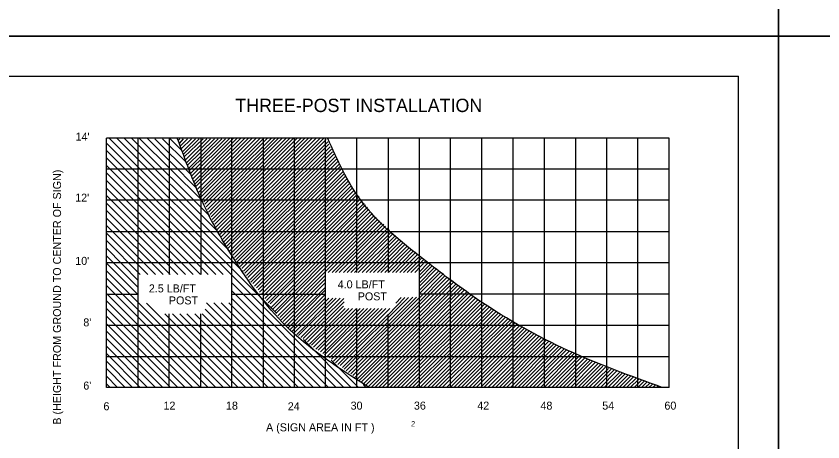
# Model space of a CAD drawing. Extents: x 644358 to 648627, y 294594 to 295782.
# Drawn here: x 645754.7 to 646056.9, y 295035.6 to 295195.1 of the extents above; entities that cross this region are included whole.
import ezdxf

# ---------------------------------------------------------------- set-up
doc = ezdxf.new("R2010")
doc.units = 0
for name, color, linetype in [('1', 7, 'Continuous'), ('10', 7, 'Continuous'), ('2', 7, 'Continuous'), ('4', 7, 'Continuous'), ('PLT-BNDY', 7, 'Continuous')]:
    doc.layers.add(name, color=color, linetype=linetype)

msp = doc.modelspace()

# ---------------------------------------------------------------- linework, layer by layer
at = {"layer": '1'}
for p, q in [((645239.31, 295172.63), (646025.31, 295172.63)), ((646025.31, 294608.63), (646025.31, 295172.63)), ((645845.96, 295090.75), (645845.96, 295090.75)), ((645859.21, 295079.5), (645859.21, 295079.5)), ((645872.21, 295067.63), (645872.21, 295067.63))]:
    msp.add_line(p, q, dxfattribs=at)
at = {"layer": '10'}
for p, q in [((645839.59, 295099.38), (645789.59, 295149.38)), ((645834.21, 295107.5), (645792.46, 295149.38)), ((645830.21, 295114.38), (645795.21, 295149.38)), ((645827.21, 295120.13), (645798.09, 295149.25)), ((645824.34, 295126), (645800.96, 295149.25)), ((645822.21, 295130.75), (645803.96, 295149.25)), ((645820.21, 295135.75), (645806.71, 295149.13)), ((645818.46, 295140.38), (645809.59, 295149.13)), ((645816.84, 295144.75), (645812.46, 295149.13)), ((645815.46, 295148.5), (645816.09, 295149.13)), ((645815.96, 295147.38), (645817.46, 295149.13)), ((645816.21, 295146.38), (645818.96, 295149.13)), ((645816.59, 295145.38), (645820.46, 295149.13)), ((645817.09, 295144.25), (645821.84, 295149.13)), ((645817.46, 295143.38), (645823.21, 295149.13)), ((645817.71, 295142.38), (645824.71, 295149.13)), ((645818.21, 295141.25), (645826.09, 295149.13)), ((645818.59, 295140.25), (645827.46, 295149.13)), ((645818.96, 295139.25), (645828.96, 295149.13)), ((645819.34, 295138.13), (645830.34, 295149.13)), ((645819.71, 295137.25), (645831.71, 295149.13)), ((645820.21, 295136.25), (645833.09, 295149.13)), ((645820.46, 295135.13), (645834.59, 295149.25)), ((645820.84, 295134.13), (645835.96, 295149.25)), ((645821.34, 295133.13), (645837.34, 295149.25)), ((645821.71, 295132.13), (645838.71, 295149.25)), ((645821.96, 295131.13), (645840.21, 295149.25)), ((645822.59, 295130.25), (645841.59, 295149.25)), ((645823.09, 295129.13), (645842.96, 295149.25)), ((645823.46, 295128.25), (645844.46, 295149.25)), ((645823.96, 295127.38), (645845.96, 295149.25)), ((645824.46, 295126.38), (645847.34, 295149.25)), ((645824.96, 295125.5), (645848.71, 295149.25)), ((645825.34, 295124.63), (645850.21, 295149.25)), ((645825.84, 295123.63), (645851.59, 295149.25)), ((645826.34, 295122.63), (645852.96, 295149.38)), ((645826.71, 295121.63), (645854.34, 295149.38)), ((645827.21, 295120.75), (645855.84, 295149.38)), ((645827.71, 295119.88), (645857.21, 295149.38)), ((645828.09, 295118.88), (645858.59, 295149.38)), ((645828.59, 295118), (645859.96, 295149.38)), ((645829.09, 295117.13), (645861.46, 295149.38)), ((645829.46, 295116), (645862.84, 295149.38)), ((645829.96, 295115.13), (645864.21, 295149.38)), ((645830.46, 295114.13), (645865.59, 295149.38)), ((645830.96, 295113.25), (645867.09, 295149.38)), ((645831.46, 295112.38), (645868.59, 295149.38)), ((645831.96, 295111.38), (645869.96, 295149.38)), ((645832.46, 295110.5), (645870.84, 295148.88)), ((645852.13, 295083.96), (645788.59, 295147.5)), ((645832.96, 295109.63), (645871.46, 295148)), ((645833.59, 295108.88), (645871.84, 295147.13)), ((645834.09, 295108.13), (645872.34, 295146.13)), ((645834.71, 295107.13), (645872.84, 295145.25)), ((645830.82, 295102.63), (645788.59, 295144.75)), ((645832.28, 295098.31), (645788.59, 295142)), ((645835.34, 295106.38), (645873.21, 295144.25)), ((645835.84, 295105.5), (645873.71, 295143.38)), ((645836.46, 295104.63), (645874.34, 295142.5)), ((645829.53, 295098.31), (645788.59, 295139.13)), ((645836.96, 295103.75), (645874.71, 295141.5)), ((645837.46, 295103), (645875.21, 295140.63)), ((645838.09, 295102.13), (645875.71, 295139.63)), ((645826.65, 295098.31), (645788.59, 295136.38)), ((645838.59, 295101.25), (645876.09, 295138.75)), ((645839.21, 295100.5), (645876.59, 295137.88)), ((645839.84, 295099.5), (645877.21, 295136.88)), ((645840.34, 295098.75), (645877.59, 295136)), ((645823.78, 295098.31), (645788.59, 295133.5)), ((645840.96, 295097.88), (645878.09, 295135.13)), ((645841.46, 295097.13), (645878.59, 295134.13)), ((645842.09, 295096.13), (645879.09, 295133.25)), ((645821.03, 295098.31), (645788.59, 295130.63)), ((645842.59, 295095.38), (645879.46, 295132.25)), ((645843.38, 295094.92), (645880.09, 295131.38)), ((645844.05, 295093.97), (645880.59, 295130.63)), ((645818.15, 295098.31), (645788.59, 295127.88)), ((645844.74, 295093.28), (645881.21, 295129.75)), ((645845.4, 295092.57), (645881.96, 295129)), ((645845.92, 295091.71), (645882.46, 295128.25)), ((645846.73, 295091.02), (645883.21, 295127.5)), ((645815.28, 295098.31), (645788.59, 295125)), ((645847.28, 295090.19), (645883.71, 295126.63)), ((645847.91, 295089.33), (645884.34, 295125.88)), ((645848.46, 295088.62), (645885.09, 295125)), ((645849.16, 295087.7), (645885.59, 295124.38)), ((645812.4, 295098.31), (645788.59, 295122.25)), ((645849.86, 295087.27), (645886.34, 295123.5)), ((645850.09, 295085.88), (645886.84, 295122.75)), ((645850.71, 295085.25), (645887.46, 295121.88)), ((645869.65, 295102.63), (645888.09, 295121.13)), ((645809.78, 295098.31), (645788.59, 295119.38)), ((645870.27, 295099.06), (645890.21, 295119)), ((645870.97, 295102.63), (645888.84, 295120.38)), ((645871.65, 295099.06), (645890.96, 295118.38)), ((645872.46, 295102.63), (645889.59, 295119.75)), ((645806.9, 295098.31), (645788.59, 295116.63)), ((645873.03, 295099.06), (645891.71, 295117.63)), ((645874.4, 295099.06), (645892.46, 295117.13)), ((645875.77, 295099.06), (645893.09, 295116.38)), ((645877.28, 295099.06), (645893.96, 295115.63)), ((645878.65, 295099.06), (645894.59, 295115)), ((645804.03, 295098.31), (645788.59, 295113.75)), ((645880.03, 295099.06), (645895.34, 295114.25)), ((645881.4, 295099.06), (645895.96, 295113.63)), ((645882.79, 295099.06), (645896.84, 295112.88)), ((645884.27, 295099.06), (645897.46, 295112.25)), ((645801.16, 295098.31), (645788.59, 295111)), ((645885.77, 295099.06), (645898.21, 295111.5)), ((645887.15, 295099.06), (645898.96, 295110.88)), ((645888.52, 295099.06), (645899.71, 295110.25)), ((645890.02, 295099.06), (645900.46, 295109.63)), ((645891.28, 295099.06), (645901.34, 295109)), ((645800.46, 295096.1), (645788.59, 295108.13)), ((645892.77, 295099.06), (645902.09, 295108.38)), ((645894.15, 295099.06), (645902.84, 295107.75)), ((645895.64, 295099.06), (645903.59, 295107.13)), ((645896.9, 295099.06), (645904.46, 295106.63)), ((645898.4, 295099.06), (645905.21, 295105.88)), ((645800.46, 295093.38), (645788.59, 295105.25)), ((645899.78, 295099.06), (645906.09, 295105.25)), ((645901.17, 295099.06), (645906.84, 295104.63)), ((645902.53, 295099.06), (645907.59, 295104)), ((645904, 295099.06), (645908.34, 295103.5)), ((645905.84, 295099.35), (645909.02, 295102.74)), ((645908.97, 295102.63), (645909.09, 295102.75)), ((645800.46, 295090.63), (645788.59, 295102.5)), ((645877.46, 295056), (645830.84, 295102.63)), ((645851.46, 295084.38), (645869.65, 295102.63)), ((645851.96, 295083.75), (645870.59, 295102.25)), ((645852.71, 295082.88), (645872.46, 295102.63)), ((645905.84, 295098), (645909.96, 295102.13)), ((645905.84, 295096.75), (645910.71, 295101.63)), ((645905.84, 295095.25), (645911.46, 295100.88)), ((645905.84, 295094), (645912.21, 295100.38)), ((645800.46, 295087.79), (645788.59, 295099.63)), ((645797.39, 295088.08), (645788.59, 295096.88)), ((645853.46, 295082.25), (645870.59, 295099.38)), ((645853.96, 295081.38), (645870.59, 295098)), ((645905.84, 295092.38), (645913.09, 295099.63)), ((645905.84, 295091.13), (645913.84, 295099.13)), ((645905.84, 295089.63), (645914.71, 295098.5)), ((645905.84, 295088.25), (645915.33, 295097.75)), ((645905.84, 295086.98), (645916.03, 295097.22)), ((645826.59, 295056), (645788.59, 295094.13)), ((645874.59, 295056), (645835.46, 295095.13)), ((645854.71, 295080.75), (645870.59, 295096.63)), ((645855.34, 295079.88), (645870.59, 295095.27)), ((645880.85, 295060.51), (645916.9, 295096.56)), ((645881.6, 295059.76), (645917.84, 295096)), ((645882.57, 295059.24), (645918.59, 295095.38)), ((645883.28, 295058.69), (645919.46, 295094.75)), ((645884.11, 295058.03), (645920.21, 295094.13)), ((645823.71, 295056), (645788.59, 295091.25)), ((645871.71, 295056), (645835.46, 295092.25)), ((645856.09, 295079.25), (645870.59, 295093.61)), ((645856.59, 295078.38), (645870.59, 295092.51)), ((645857.34, 295077.75), (645870.59, 295091)), ((645884.71, 295057.25), (645920.96, 295093.5)), ((645885.59, 295056.75), (645921.71, 295092.88)), ((645886.59, 295056.25), (645922.59, 295092.38)), ((645887.84, 295056.13), (645923.46, 295091.75)), ((645889.21, 295056.13), (645924.21, 295091.25)), ((645820.96, 295056), (645788.59, 295088.5)), ((645829.46, 295056), (645797.2, 295088.26)), ((645832.34, 295056), (645800.41, 295087.83)), ((645857.71, 295056), (645825.96, 295087.75)), ((645860.46, 295056), (645828.73, 295087.74)), ((645863.21, 295056), (645831.48, 295087.74)), ((645866.09, 295056), (645834.35, 295087.74)), ((645868.84, 295056), (645835.46, 295089.38)), ((645857.96, 295077), (645870.59, 295089.63)), ((645858.59, 295076.25), (645871.79, 295089.45)), ((645859.82, 295075.87), (645873.29, 295089.45)), ((645860.5, 295075.41), (645874.65, 295089.45)), ((645861.38, 295074.67), (645876.04, 295089.45)), ((645862.26, 295074.29), (645877.46, 295089.38)), ((645863.03, 295073.57), (645877.59, 295088.13)), ((645876.05, 295064.21), (645901.64, 295089.65)), ((645876.91, 295063.45), (645903.29, 295089.83)), ((645877.57, 295062.85), (645904.66, 295089.83)), ((645878.34, 295062.25), (645905.92, 295089.83)), ((645879.22, 295061.64), (645907.42, 295089.83)), ((645880.08, 295061.12), (645908.67, 295089.83)), ((645890.59, 295056.13), (645925.21, 295090.63)), ((645891.96, 295056.13), (645925.96, 295090.13)), ((645893.46, 295056.13), (645926.84, 295089.5)), ((645894.14, 295083.33), (645900.34, 295089.75)), ((645894.84, 295056.13), (645927.71, 295088.88)), ((645896.21, 295056.13), (645928.59, 295088.5)), ((645896.96, 295087.63), (645898.96, 295089.75)), ((645897.59, 295056.13), (645929.34, 295087.88)), ((645818.09, 295056), (645788.59, 295085.63)), ((645835.09, 295056), (645803.58, 295087.51)), ((645854.84, 295056), (645825.48, 295085.36)), ((645863.89, 295073.05), (645877.34, 295086.5)), ((645864.58, 295072.25), (645877.93, 295085.6)), ((645865.38, 295071.78), (645879.33, 295085.6)), ((645866.15, 295071.06), (645880.68, 295085.6)), ((645866.95, 295070.37), (645882.18, 295085.6)), ((645867.83, 295069.99), (645883.58, 295085.6)), ((645868.72, 295069.38), (645884.93, 295085.6)), ((645869.57, 295068.75), (645886.29, 295085.6)), ((645870.23, 295068.15), (645887.68, 295085.6)), ((645871.17, 295067.59), (645889.04, 295085.6)), ((645872.05, 295067.1), (645890.42, 295085.6)), ((645872.88, 295066.55), (645891.8, 295085.6)), ((645873.59, 295065.89), (645893.17, 295085.6)), ((645874.34, 295065.25), (645894.68, 295085.6)), ((645898.96, 295056.13), (645930.21, 295087.25)), ((645900.46, 295056.13), (645931.09, 295086.75)), ((645901.84, 295056.13), (645931.84, 295086.13)), ((645903.21, 295056.13), (645932.84, 295085.63)), ((645904.59, 295056.13), (645933.59, 295085.13)), ((645815.34, 295056), (645788.59, 295082.75)), ((645837.84, 295056), (645810.38, 295083.59)), ((645840.71, 295056), (645813.25, 295083.59)), ((645843.46, 295056), (645816, 295083.59)), ((645846.34, 295056), (645818.63, 295083.59)), ((645849.09, 295056), (645821.63, 295083.59)), ((645851.96, 295056), (645824.38, 295083.59)), ((645875.23, 295064.64), (645894.09, 295083.38)), ((645906.09, 295056.13), (645934.46, 295084.5)), ((645907.46, 295056.13), (645935.34, 295084)), ((645908.96, 295056.13), (645936.09, 295083.38)), ((645910.34, 295056.13), (645937.09, 295082.88)), ((645911.71, 295056.13), (645937.96, 295082.38)), ((645913.09, 295056.13), (645938.96, 295081.88)), ((645812.59, 295056), (645788.59, 295079.88)), ((645914.46, 295056.13), (645939.84, 295081.38)), ((645915.96, 295056), (645940.59, 295080.88)), ((645917.34, 295056), (645941.59, 295080.38)), ((645918.71, 295056), (645942.46, 295079.88)), ((645920.09, 295056), (645943.46, 295079.38)), ((645921.46, 295056), (645944.34, 295078.88)), ((645809.71, 295056), (645788.59, 295077.13)), ((645922.84, 295056), (645945.21, 295078.38)), ((645924.34, 295056), (645946.09, 295077.88)), ((645925.71, 295056), (645946.96, 295077.38)), ((645927.09, 295056), (645947.96, 295076.88)), ((645928.59, 295056), (645948.84, 295076.38)), ((645929.96, 295056), (645949.71, 295075.88)), ((645806.96, 295056), (645788.59, 295074.38)), ((645880.21, 295056), (645862.3, 295073.91)), ((645931.46, 295056), (645950.71, 295075.38)), ((645932.84, 295056), (645951.59, 295074.88)), ((645934.21, 295056), (645952.46, 295074.38)), ((645935.59, 295056), (645953.34, 295073.88)), ((645936.96, 295056), (645954.21, 295073.38)), ((645938.34, 295056), (645955.21, 295072.88)), ((645803.96, 295056), (645788.59, 295071.5)), ((645939.84, 295056), (645956.09, 295072.38)), ((645941.21, 295056), (645957.09, 295072)), ((645942.59, 295056), (645958.09, 295071.5)), ((645943.96, 295056), (645958.96, 295071.13)), ((645945.34, 295056), (645960.09, 295070.63)), ((645946.84, 295056), (645960.96, 295070.25)), ((645948.21, 295056), (645961.96, 295069.75)), ((645801.21, 295056), (645788.59, 295068.75)), ((645949.59, 295056), (645962.96, 295069.25)), ((645951.09, 295056), (645963.84, 295068.88)), ((645952.46, 295056), (645964.84, 295068.5)), ((645953.84, 295056), (645965.84, 295068)), ((645955.34, 295056), (645966.71, 295067.63)), ((645956.71, 295056), (645967.71, 295067.13)), ((645958.09, 295056), (645968.71, 295066.63)), ((645798.34, 295056), (645788.59, 295065.88)), ((645882.96, 295056), (645872.71, 295066.26)), ((645959.46, 295056), (645969.71, 295066.25)), ((645960.84, 295056), (645970.59, 295065.88)), ((645962.34, 295056), (645971.59, 295065.38)), ((645963.71, 295056), (645972.59, 295064.88)), ((645965.09, 295056), (645973.59, 295064.5)), ((645966.46, 295056), (645974.46, 295064)), ((645967.84, 295056), (645975.46, 295063.63)), ((645795.59, 295056), (645788.59, 295063.13)), ((645969.21, 295056), (645976.59, 295063.13)), ((645970.71, 295056), (645977.59, 295062.88)), ((645972.09, 295056), (645978.59, 295062.5)), ((645973.59, 295056), (645979.59, 295062.13)), ((645974.96, 295056), (645980.71, 295061.63)), ((645976.34, 295056), (645981.71, 295061.38)), ((645977.84, 295056), (645982.71, 295061)), ((645979.21, 295056), (645983.84, 295060.63)), ((645792.71, 295056), (645788.59, 295060.25)), ((645980.59, 295056), (645984.84, 295060.25)), ((645981.96, 295056), (645985.84, 295059.88)), ((645983.34, 295056), (645986.96, 295059.5)), ((645984.71, 295056), (645987.96, 295059.13)), ((645986.21, 295056), (645988.96, 295058.75)), ((645987.59, 295056), (645990.09, 295058.5)), ((645988.96, 295056), (645991.09, 295058.13)), ((645990.34, 295056), (645992.09, 295057.63)), ((645789.96, 295056), (645788.59, 295057.38)), ((645885.84, 295056), (645884.71, 295057.13)), ((645991.71, 295056), (645993.09, 295057.25)), ((645993.21, 295056), (645994.21, 295057)), ((645994.59, 295056), (645995.21, 295056.63)), ((645996.09, 295056), (645996.21, 295056.25))]:
    msp.add_line(p, q, dxfattribs=at)
at = {"layer": '2'}
for p, q in [((645999.34, 295149.38), (645788.59, 295149.38)), ((645788.59, 295056), (645788.59, 295149.38)), ((645800.46, 295102.63), (645800.46, 295149.38)), ((645812.09, 295149.38), (645812.09, 295098.31)), ((645823.84, 295149.38), (645823.84, 295098.31)), ((645835.46, 295090.88), (645835.46, 295149.38)), ((645847.34, 295055.88), (645847.34, 295149.38)), ((645858.96, 295056), (645858.96, 295149.38)), ((645870.59, 295090.88), (645870.59, 295149.38)), ((645882.34, 295099.06), (645882.34, 295149.38)), ((645894.09, 295149.38), (645894.09, 295099.06)), ((645905.84, 295102.63), (645905.84, 295149.38)), ((645917.46, 295055.88), (645917.46, 295149.38)), ((645929.09, 295056), (645929.09, 295149.38)), ((645940.84, 295055.88), (645940.84, 295149.38)), ((645952.59, 295056), (645952.59, 295149.38)), ((645964.34, 295055.88), (645964.34, 295149.38)), ((645975.96, 295056), (645975.96, 295149.38)), ((645987.59, 295055.88), (645987.59, 295149.38)), ((645999.34, 295056), (645999.34, 295149.38)), ((645999.34, 295137.75), (645788.84, 295137.75)), ((645999.34, 295126.13), (645788.84, 295126.13)), ((645999.34, 295114.25), (645788.84, 295114.25)), ((645894.09, 295102.63), (645788.84, 295102.63)), ((645800.46, 295055.88), (645800.46, 295102.63)), ((645999.34, 295102.63), (645894.09, 295102.63)), ((645905.84, 295056), (645905.84, 295102.63)), ((645788.84, 295090.88), (645800.46, 295090.88)), ((645835.46, 295056), (645835.46, 295090.88)), ((645835.46, 295090.88), (645870.59, 295090.88)), ((645870.59, 295056), (645870.59, 295090.88)), ((645999.34, 295090.88), (645905.84, 295090.88)), ((645882.34, 295056), (645882.34, 295085.6)), ((645812.09, 295056), (645812.09, 295083.59)), ((645823.84, 295056), (645823.84, 295083.59)), ((645894.09, 295056), (645894.09, 295083.38)), ((645999.34, 295079.25), (645788.59, 295079.25)), ((645999.34, 295067.5), (645788.84, 295067.5)), ((645999.34, 295056), (645788.59, 295056))]:
    msp.add_line(p, q, dxfattribs=at)
at = {"layer": '4'}
msp.add_line((645996.71, 295056), (645996.71, 295056), dxfattribs=at)
for points in [[(645886.71, 295056.13), (645857.21, 295077.63), (645837.09, 295102.88), (645824.34, 295125.88), (645815.21, 295149.13)], [(645996.71, 295056), (645961.34, 295069.88), (645928.46, 295088.38), (645908.59, 295103), (645883.84, 295126.13), (645871.46, 295149.25)]]:
    msp.add_spline(points, degree=3, dxfattribs=at)
at = {"layer": 'PLT-BNDY'}
for points in [[(645199.31, 295781.63), (646040.31, 295781.63), (646040.31, 295187.63), (645199.31, 295187.63)], [(646040.31, 295781.63), (646881.31, 295781.63), (646881.31, 295187.63), (646040.31, 295187.63)], [(645199.31, 295187.63), (646040.31, 295187.63), (646040.31, 294593.63), (645199.31, 294593.63)], [(646040.31, 295187.63), (646881.31, 295187.63), (646881.31, 294593.63), (646040.31, 294593.63)]]:
    msp.add_lwpolyline(points, close=True, dxfattribs=at)

# ---------------------------------------------------------------- texts
at = {"layer": '2'}
for s, height, p in [('THREE-POST INSTALLATION', 5, (645836.81, 295159.18)), ('6', 3, (645787.42, 295047.43)), ('12', 3, (645809.91, 295047.68)), ('18', 3, (645833.32, 295047.68)), ('24', 3, (645856.47, 295047.43)), ('30', 3, (645880, 295047.68)), ('36', 3, (645903.71, 295047.68)), ('42', 3, (645927.45, 295047.68)), ('48', 3, (645951.11, 295047.68)), ('54', 3, (645974.26, 295047.68)), ('60', 3, (645997.54, 295047.68))]:
    msp.add_text(s, height=height, dxfattribs=at).set_placement(p)
at = {"layer": '4'}
for s, height, p in [("14'", 3, (645776.98, 295148.45)), ("12'", 3, (645776.84, 295125.6)), ("10'", 3, (645776.86, 295101.92)), ('2.5 LB/FT', 3, (645804.43, 295091.6)), ('4.0 LB/FT', 3, (645875.18, 295093.12)), ('POST', 3, (645882.68, 295088.62)), ('POST', 3, (645811.93, 295087.1)), ("8'", 3, (645779.88, 295078.87)), ("6'", 3, (645779.87, 295055.18)), ('A (SIGN AREA IN FT )', 3.005, (645848.33, 295039.55)), ('2', 2, (645902.64, 295041.37))]:
    msp.add_text(s, height=height, dxfattribs=at).set_placement(p)
msp.add_text(' B (HEIGHT FROM GROUND TO CENTER OF SIGN)', height=3.005, rotation=90, dxfattribs=at).set_placement((645771.54, 295040.93))

doc.saveas('drawing.dxf')
